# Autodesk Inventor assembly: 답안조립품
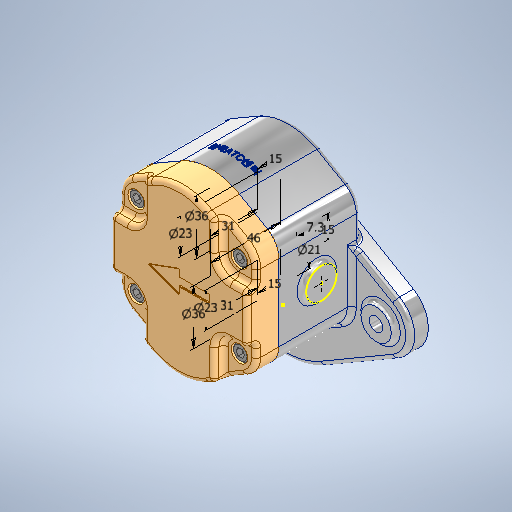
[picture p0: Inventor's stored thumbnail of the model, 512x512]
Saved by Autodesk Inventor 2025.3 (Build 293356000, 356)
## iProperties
Created: 2025-11
Part Number: 답안조립품
Document SubType Name: Assembly
Designer: PC-13
Author: PC-13
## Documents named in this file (9)
- C:\Users\PC-13\Desktop\751103V1004\답안조립품.iam
- C:\Users\PC-13\Desktop\751103V1004\답안본체.ipt
- C:\Users\PC-13\Desktop\751103V1004\DU 부시\DU 부시.ipt
- C:\Users\PC-13\Desktop\751103V1004\스퍼기어\스퍼기어.ipt
- C:\Users\PC-13\Desktop\751103V1004\구동기어\구동기어\구동기어.ipt
- C:\Users\PC-13\Desktop\751103V1004\6각 구멍붙이 볼트 M6x16\6각 구멍붙이 볼트 M6x16\6각 구멍붙이 볼트 M6x16.ipt
- C:\Users\PC-13\Desktop\751103V1004\커버\커버\커버.ipt
- C:\Users\PC-13\Desktop\751103V1004\오일 실 16 30 7\오일 실 16 30 7\오일 실 16 30 7.ipt
- C:\Users\PC-13\Desktop\751103V1004\실링\실링\실링.ipt
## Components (9 placed, 3 different names)
1. DU 부시:1
2. DU 부시:2
3. DU 부시:3
4. DU 부시:4
5. 구동기어:1
6. 6각 구멍붙이 볼트 M6x16:1
7. 6각 구멍붙이 볼트 M6x16:2
8. 6각 구멍붙이 볼트 M6x16:3
9. 6각 구멍붙이 볼트 M6x16:4
